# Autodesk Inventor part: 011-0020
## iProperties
Created: 2007-02
Part Number: 011-0020
Document SubType Name: Modeling
Designer: GG5883
Project: GDB380
Material: 45 Si Cr Mo 5
Description: Ressort de déverrouillage
Stock Number: 11-0020
Author: Gilles GLEMAREC
Revision Number: 00
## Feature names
1. Hélicoïde1
2. Scission1
3. Scission2
